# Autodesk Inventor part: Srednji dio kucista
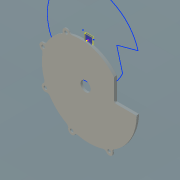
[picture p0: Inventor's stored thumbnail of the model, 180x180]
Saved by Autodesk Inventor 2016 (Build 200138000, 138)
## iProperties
Created: 2015-04
Part Number: Srednji dio kucista
Material: Generic
Document SubType Name: Modeling
Designer: Uglješa
Density: 1 g/cm^3
Appearance: Default
Mass: 391.207 g
Surface Area: 994.686 cm^2
Volume: 391.207 cm^3
Author: Uglješa
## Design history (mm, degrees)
sketch "Sketch1"
  geometry: L1 (76.246, -47.553)-(76.198, -109.059) reference; L2 (136.981, -109.107)-(76.198, -109.059) reference; A1 r 119.037 centre (-15.855, -122.966) between (76.246, -47.553) and (0.079, -5) reference; A2 r 127.464 centre (9.536, -106.9) between (-0.099, -234) and (136.981, -109.107) reference; A3 r 127.292 centre (10.292, -107.133) between (-117, -106.909) and (-0.099, -234) reference; 2 further points
  constraints: 6 point on circle, 4 end point, 3 centre point, 25 other
workplane "Work Plane1"
sketch "Sketch3"
  geometry: 1 further point
workplane "Work Plane2"
extrude "Extrusion3" new body sketch "Sketch1" distance "d6" = 4; taper "d7" = 0 deg; dims "d104" = 4, "d105" = 0
workplane "Work Plane3"
sketch "Sketch9"
  geometry: C1 r 14 at (0, -107); C2 r 2.65 at (0, -107) reference; 1 further point
  constraints: 1 centre point, 1 concentric
  dimensions: "d31" = 28 diameter of C1
extrude "Extrusion7" cut sketch "Sketch9" stored distance "d32" = 80; taper "d33" = 0 deg
sketch "Sketch17"
  geometry: 1 further point
sketch "Sketch18"
  geometry: L1 (78.245, -48.794)-(78.204, -102.061) reference; L2 (83.2, -107.065)-(134.9, -107.105) reference; C1 r 4.5 at (-110.388, -165.646) reference; C2 r 4.5 at (-38.051, -231.307) reference; C3 r 4.5 at (64.746, -228.869) reference; C4 r 14 at (0, -107); A1 r 5 centre (73.245, -48.79) between (78.245, -48.794) and (77.152, -45.669) reference; A2 r 5 centre (83.204, -102.065) between (78.204, -102.061) and (83.2, -107.065) reference; A3 r 10 centre (64.746, -228.869) between (55.915, -233.561) and (73.577, -224.177) reference; A4 r 130.357 centre (9.643, -107.008) between (-0.101, -237) and (46.96, -231.909) reference; A5 r 130.417 centre (10.417, -107.008) between (-21.515, -233.455) and (-0.101, -237) reference; A6 r 10 centre (-38.051, -231.307) between (-47.613, -228.38) and (-28.489, -234.234) reference; A7 r 130.417 centre (10.417, -107.008) between (-98.388, -178.91) and (-52.658, -221.157) reference; A8 r 10 centre (-110.388, -165.646) between (-115.08, -156.815) and (-105.697, -174.477) reference; A9 r 130.417 centre (10.417, -107.008) between (-120, -106.907) and (-113.516, -147.62) reference; A10 r 10 centre (-116.657, -71.291) between (-113.73, -61.729) and (-119.584, -80.853) reference; A11 r 10 centre (-53.485, -6.326) between (-44.654, -1.634) and (-62.316, -11.017) reference; A12 r 4.5 centre (-116.657, -71.291) between (-115.23, -75.559) and (-112.889, -68.831) reference; A13 r 4.5 centre (-116.657, -71.291) between (-112.889, -68.831) and (-115.23, -75.559) reference; A14 r 4.5 centre (-53.485, -6.326) between (-56.289, -9.846) and (-49.073, -7.207) reference; A15 r 4.5 centre (-53.485, -6.326) between (-49.073, -7.207) and (-56.289, -9.846) reference; A16 r 119.037 centre (-15.853, -119.966) between (67.678, -35.157) and (0.082, -2) reference; A17 r 130.357 centre (9.643, -107.008) between (78.06, -217.968) and (139.892, -112.308) reference; 4 further points
  constraints: 34 point on circle, 21 centre point, 4 end point, 118 other
  dimensions: "d101" = 28 diameter of C4
sketch "Sketch19"
  geometry: C1 r 14 at (0, -107) reference; C2 r 67.5 at (0, -107); 1 further point
  constraints: 1 centre point, 1 coincident
  dimensions: "d95" = 135 diameter of C2
extrude "Extrusion15" cut sketch "Sketch19" distance "d96" = 5; taper "d97" = 0 deg
extrude "Extrusion16" join sketch "Sketch18" distance "d102" = 3; taper "d103" = 0 deg
fillet "Fillet6" dims "d106" = 2
body "Solid1"
